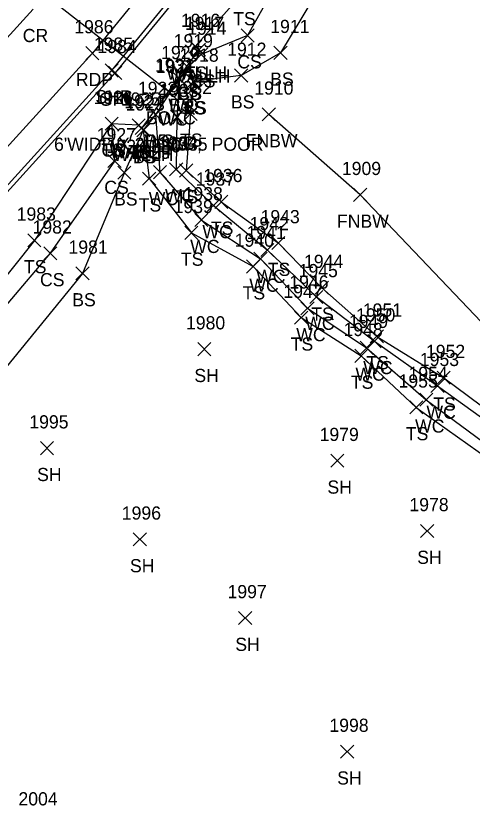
# Model space of a CAD drawing. Extents: x 1520648 to 1523413, y 732854 to 735518.
# Drawn here: x 1522252.1 to 1522321.3, y 733840.7 to 733961.6 of the extents above; entities that cross this region are included whole.
import ezdxf

# ---------------------------------------------------------------- set-up
doc = ezdxf.new("R2010")
doc.units = 0
for name, color, linetype in [('D_A', 7, 'Continuous'), ('D_C', 7, 'Continuous'), ('D_I', 7, 'Continuous'), ('D_TIC', 7, 'Continuous'), ('DDEFAULT', 7, 'Continuous'), ('DHW', 7, 'Continuous'), ('L_A', 7, 'Continuous'), ('L_I', 7, 'Continuous'), ('L_TIC', 7, 'Continuous'), ('LAWE', 7, 'Continuous'), ('LELB', 7, 'Continuous'), ('LFNC', 7, 'Continuous'), ('P_A', 7, 'Continuous'), ('P_I', 7, 'Continuous'), ('P_TIC', 7, 'Continuous'), ('PET', 7, 'Continuous'), ('PRC', 7, 'Continuous'), ('PSP', 7, 'Continuous'), ('R_A', 7, 'Continuous'), ('R_I', 7, 'Continuous'), ('R_TIC', 7, 'Continuous'), ('RGR', 7, 'Continuous')]:
    doc.layers.add(name, color=color, linetype=linetype)

msp = doc.modelspace()

# ---------------------------------------------------------------- linework, layer by layer
at = {"layer": 'D_TIC'}
for points in [[(1522278.32, 733955.93), (1522280.32, 733957.93)], [(1522280.32, 733955.93), (1522278.32, 733957.93)], [(1522278.87, 733955.47), (1522280.87, 733957.47)], [(1522280.87, 733955.47), (1522278.87, 733957.47)], [(1522274.31, 733949.11), (1522276.31, 733951.11)], [(1522276.31, 733949.11), (1522274.31, 733951.11)], [(1522269.74, 733943.98), (1522271.74, 733945.98)], [(1522271.74, 733943.98), (1522269.74, 733945.98)], [(1522270.22, 733943.58), (1522272.22, 733945.58)], [(1522272.22, 733943.58), (1522270.22, 733945.58)]]:
    msp.add_lwpolyline(points, dxfattribs=at)
at = {"layer": 'DDEFAULT'}
msp.add_lwpolyline([(1522243.41, 733975.06), (1522275.31, 733950.11)], dxfattribs=at)
at = {"layer": 'DHW'}
msp.add_lwpolyline([(1522279.32, 733956.93), (1522279.87, 733956.47), (1522271.22, 733944.58), (1522270.74, 733944.98)], dxfattribs=at)
at = {"layer": 'L_TIC'}
for points in [[(1522286.26, 733957.62), (1522288.26, 733959.62)], [(1522288.26, 733957.62), (1522286.26, 733959.62)], [(1522278.32, 733955.93), (1522280.32, 733957.93)], [(1522280.32, 733955.93), (1522278.32, 733957.93)], [(1522279.22, 733954.73), (1522281.22, 733956.73)], [(1522281.22, 733954.73), (1522279.22, 733956.73)], [(1522291.25, 733955), (1522293.25, 733957)], [(1522293.25, 733955), (1522291.25, 733957)], [(1522277.18, 733952.83), (1522279.18, 733954.83)], [(1522279.18, 733952.83), (1522277.18, 733954.83)], [(1522277.18, 733952.83), (1522279.18, 733954.83)], [(1522279.18, 733952.83), (1522277.18, 733954.83)], [(1522275.92, 733951.03), (1522277.92, 733953.03)], [(1522277.92, 733951.03), (1522275.92, 733953.03)], [(1522275.92, 733951.03), (1522277.92, 733953.03)], [(1522277.92, 733951.03), (1522275.92, 733953.03)], [(1522275.92, 733951.03), (1522277.92, 733953.03)], [(1522277.92, 733951.03), (1522275.92, 733953.03)], [(1522278.05, 733950.64), (1522280.05, 733952.64)], [(1522280.05, 733950.64), (1522278.05, 733952.64)], [(1522278.05, 733950.64), (1522280.05, 733952.64)], [(1522280.05, 733950.64), (1522278.05, 733952.64)], [(1522285.28, 733951.54), (1522287.28, 733953.54)], [(1522287.28, 733951.54), (1522285.28, 733953.54)], [(1522274.47, 733948.94), (1522276.47, 733950.94)], [(1522276.47, 733948.94), (1522274.47, 733950.94)], [(1522277.6, 733945.73), (1522279.6, 733947.73)], [(1522279.6, 733945.73), (1522277.6, 733947.73)], [(1522272.3, 733945.59), (1522274.3, 733947.59)], [(1522274.3, 733945.59), (1522272.3, 733947.59)], [(1522272.3, 733945.59), (1522274.3, 733947.59)], [(1522274.3, 733945.59), (1522272.3, 733947.59)], [(1522275.54, 733945.28), (1522277.54, 733947.28)], [(1522277.54, 733945.28), (1522275.54, 733947.28)], [(1522289.49, 733945.64), (1522291.49, 733947.64)], [(1522291.49, 733945.64), (1522289.49, 733947.64)], [(1522265.63, 733944.22), (1522267.63, 733946.22)], [(1522267.63, 733944.22), (1522265.63, 733946.22)], [(1522265.63, 733944.22), (1522267.63, 733946.22)], [(1522267.63, 733944.22), (1522265.63, 733946.22)], [(1522269.74, 733943.98), (1522271.74, 733945.98)], [(1522271.74, 733943.98), (1522269.74, 733945.98)], [(1522270.43, 733943.22), (1522272.43, 733945.22)], [(1522272.43, 733943.22), (1522270.43, 733945.22)], [(1522270.43, 733943.22), (1522272.43, 733945.22)], [(1522272.43, 733943.22), (1522270.43, 733945.22)], [(1522266.06, 733938.56), (1522268.06, 733940.56)], [(1522268.06, 733938.56), (1522266.06, 733940.56)], [(1522275.43, 733937.29), (1522277.43, 733939.29)], [(1522277.43, 733937.29), (1522275.43, 733939.29)], [(1522267.56, 733936.8), (1522269.56, 733938.8)], [(1522269.56, 733936.8), (1522267.56, 733938.8)], [(1522272.96, 733936.86), (1522274.96, 733938.86)], [(1522274.96, 733936.86), (1522272.96, 733938.86)], [(1522276.94, 733937.13), (1522278.94, 733939.13)], [(1522278.94, 733937.13), (1522276.94, 733939.13)], [(1522271.32, 733935.89), (1522273.32, 733937.89)], [(1522273.32, 733935.89), (1522271.32, 733937.89)], [(1522303.34, 733933.43), (1522305.34, 733935.43)], [(1522305.34, 733933.43), (1522303.34, 733935.43)], [(1522281.09, 733931.82), (1522283.09, 733933.82)], [(1522283.09, 733931.82), (1522281.09, 733933.82)], [(1522282.27, 733932.36), (1522284.27, 733934.36)], [(1522284.27, 733932.36), (1522282.27, 733934.36)], [(1522279.24, 733929.59), (1522281.24, 733931.59)], [(1522281.24, 733929.59), (1522279.24, 733931.59)], [(1522277.73, 733927.65), (1522279.73, 733929.65)], [(1522279.73, 733927.65), (1522277.73, 733929.65)], [(1522253.91, 733926.51), (1522255.91, 733928.51)], [(1522255.91, 733926.51), (1522253.91, 733928.51)], [(1522290.91, 733926.11), (1522292.91, 733928.11)], [(1522292.91, 733926.11), (1522290.91, 733928.11)], [(1522256.32, 733924.54), (1522258.32, 733926.54)], [(1522258.32, 733924.54), (1522256.32, 733926.54)], [(1522289.25, 733925.05), (1522291.25, 733927.05)], [(1522291.25, 733925.05), (1522289.25, 733927.05)], [(1522288.21, 733923.7), (1522290.21, 733925.7)], [(1522290.21, 733923.7), (1522288.21, 733925.7)], [(1522287.09, 733922.54), (1522289.09, 733924.54)], [(1522289.09, 733922.54), (1522287.09, 733924.54)], [(1522261.2, 733921.49), (1522263.2, 733923.49)], [(1522263.2, 733921.49), (1522261.2, 733923.49)], [(1522297.51, 733919.32), (1522299.51, 733921.32)], [(1522299.51, 733919.32), (1522297.51, 733921.32)], [(1522296.69, 733917.92), (1522298.69, 733919.92)], [(1522298.69, 733917.92), (1522296.69, 733919.92)], [(1522295.34, 733916.19), (1522297.34, 733918.19)], [(1522297.34, 733916.19), (1522295.34, 733918.19)], [(1522294.38, 733914.77), (1522296.38, 733916.77)], [(1522296.38, 733914.77), (1522294.38, 733916.77)], [(1522305.87, 733911.93), (1522307.87, 733913.93)], [(1522307.87, 733911.93), (1522305.87, 733913.93)], [(1522305.5, 733911.19), (1522307.5, 733913.19)], [(1522307.5, 733911.19), (1522305.5, 733913.19)], [(1522279.69, 733909.99), (1522281.69, 733911.99)], [(1522281.69, 733909.99), (1522279.69, 733911.99)], [(1522304.32, 733910.2), (1522306.32, 733912.2)], [(1522306.32, 733910.2), (1522304.32, 733912.2)], [(1522303.51, 733908.97), (1522305.51, 733910.97)], [(1522305.51, 733908.97), (1522303.51, 733910.97)], [(1522316.01, 733905.65), (1522318.01, 733907.65)], [(1522318.01, 733905.65), (1522316.01, 733907.65)], [(1522315.08, 733904.42), (1522317.08, 733906.42)], [(1522317.08, 733904.42), (1522315.08, 733906.42)], [(1522313.37, 733902.31), (1522315.37, 733904.31)], [(1522315.37, 733902.31), (1522313.37, 733904.31)], [(1522311.85, 733901.15), (1522313.85, 733903.15)], [(1522313.85, 733901.15), (1522311.85, 733903.15)], [(1522255.83, 733894.95), (1522257.83, 733896.95)], [(1522257.83, 733894.95), (1522255.83, 733896.95)], [(1522299.88, 733893.04), (1522301.88, 733895.04)], [(1522301.88, 733893.04), (1522299.88, 733895.04)], [(1522313.5, 733882.38), (1522315.5, 733884.38)], [(1522315.5, 733882.38), (1522313.5, 733884.38)], [(1522269.92, 733881.1), (1522271.92, 733883.1)], [(1522271.92, 733881.1), (1522269.92, 733883.1)], [(1522285.9, 733869.16), (1522287.9, 733871.16)], [(1522287.9, 733869.16), (1522285.9, 733871.16)], [(1522301.36, 733848.87), (1522303.36, 733850.87)], [(1522303.36, 733848.87), (1522301.36, 733850.87)]]:
    msp.add_lwpolyline(points, dxfattribs=at)
at = {"layer": 'LAWE'}
for points in [[(1522276.92, 733952.03), (1522275.47, 733949.94), (1522273.3, 733946.59), (1522273.96, 733937.86), (1522280.24, 733930.59), (1522289.21, 733924.7), (1522296.34, 733917.19), (1522305.32, 733911.2), (1522314.37, 733903.31), (1522328.27, 733893.01), (1522336.91, 733884.45), (1522339.19, 733873.29), (1522347.79, 733869.61), (1522363.19, 733860.75)], [(1522276.92, 733952.03), (1522276.54, 733946.28), (1522276.43, 733938.29), (1522282.09, 733932.82), (1522290.25, 733926.05), (1522297.69, 733918.92), (1522306.5, 733912.19), (1522316.08, 733905.42), (1522329.42, 733895.81), (1522338.19, 733885.32), (1522341.63, 733873.61), (1522347.73, 733871.15), (1522364.75, 733862.12)]]:
    msp.add_lwpolyline(points, dxfattribs=at)
at = {"layer": 'LELB'}
for points in [[(1522399.21, 734122.54), (1522383.71, 734100.99), (1522356.24, 734060.92), (1522336.35, 734027.13), (1522331.32, 734016.25), (1522299.59, 733987.37), (1522286.66, 733965.18), (1522279.32, 733956.93)], [(1522401.8, 734120.85), (1522386.75, 734098.22), (1522361.49, 734057.24), (1522340.39, 734023.47), (1522334.23, 734014.82), (1522302.26, 733985.56), (1522287.26, 733958.62), (1522280.22, 733955.73), (1522278.18, 733953.83)], [(1522392.7, 734094.89), (1522365.31, 734053.94), (1522345.12, 734021), (1522336.91, 734010.39), (1522307.1, 733980.69), (1522292.25, 733956), (1522286.28, 733952.54), (1522279.05, 733951.64), (1522278.18, 733953.83), (1522276.92, 733952.03)], [(1522279.05, 733951.64), (1522278.6, 733946.73), (1522277.94, 733938.13), (1522283.27, 733933.36), (1522291.91, 733927.11), (1522298.51, 733920.32), (1522306.87, 733912.93), (1522317.01, 733906.65), (1522330.24, 733896.82), (1522339.12, 733885.66), (1522342.73, 733873.76), (1522348.54, 733872.47), (1522366.14, 733862.6)], [(1522273.3, 733946.59), (1522271.43, 733944.22), (1522268.56, 733937.8), (1522262.2, 733922.49), (1522248.35, 733905.54), (1522225.71, 733875.09), (1522211.03, 733857.35), (1522192.48, 733835.82), (1522170.81, 733810.34), (1522151.93, 733786.41), (1522130.42, 733759.83), (1522111.64, 733741.03), (1522100.77, 733725.2)], [(1522266.63, 733945.22), (1522267.06, 733939.56), (1522257.32, 733925.54), (1522244.42, 733910.4), (1522223.41, 733883.18), (1522189.15, 733838.76), (1522168.77, 733813.86), (1522150.13, 733789.06), (1522128.4, 733762.92), (1522110.49, 733741.99), (1522098.34, 733726.66), (1522093.01, 733716.82)], [(1522270.74, 733944.98), (1522266.63, 733945.22), (1522254.91, 733927.51), (1522242.52, 733911.99), (1522219.52, 733884.24), (1522186.7, 733842.89), (1522166.07, 733817.07), (1522164.2, 733814.35), (1522137.24, 733813.36), (1522122.6, 733811.13)], [(1522271.43, 733944.22), (1522272.32, 733936.89), (1522278.73, 733928.65), (1522288.09, 733923.54), (1522295.38, 733915.77), (1522304.51, 733909.97), (1522312.85, 733902.15), (1522326.96, 733892.08), (1522335.67, 733883.7), (1522338.12, 733872.97), (1522347.65, 733868.91), (1522362.14, 733859.54)]]:
    msp.add_lwpolyline(points, dxfattribs=at)
at = {"layer": 'LFNC'}
msp.add_lwpolyline([(1522367.19, 733867.69), (1522349.23, 733888.51), (1522325.8, 733911.89), (1522304.34, 733934.43), (1522290.49, 733946.64)], dxfattribs=at)
at = {"layer": 'P_TIC'}
for points in [[(1522262.71, 733954.95), (1522264.71, 733956.95)], [(1522264.71, 733954.95), (1522262.71, 733956.95)], [(1522265.63, 733952.31), (1522267.63, 733954.31)], [(1522267.63, 733952.31), (1522265.63, 733954.31)]]:
    msp.add_lwpolyline(points, dxfattribs=at)
at = {"layer": 'PET'}
msp.add_lwpolyline([(1522293.19, 733992.18), (1522263.71, 733955.95), (1522232.46, 733921.59), (1522205.93, 733894.99), (1522171.68, 733864.45), (1522150.76, 733846.95), (1522111.89, 733818.73), (1522077.26, 733795.56), (1522046.35, 733777.35), (1522014.71, 733760.04), (1521992.39, 733748.52), (1521963.75, 733735.05), (1521947.25, 733727.94), (1521903.49, 733710.07), (1521845.39, 733690.65), (1521824.85, 733681.25), (1521803.81, 733674.87), (1521790.98, 733674.84), (1521764.05, 733667.92), (1521729.46, 733658.42), (1521691.16, 733648.14)], dxfattribs=at)
at = {"layer": 'PRC'}
msp.add_lwpolyline([(1522254.71, 733962.62), (1522224.2, 733929), (1522197.91, 733903), (1522164.25, 733873.02), (1522142.54, 733855.17), (1522104.41, 733827.43), (1522070.85, 733804.7), (1522039.57, 733786.25), (1522009.6, 733770.04), (1521986.99, 733758.56), (1521958.12, 733745.43), (1521942.23, 733738.37), (1521896.32, 733720.33), (1521857.71, 733706.32), (1521841.62, 733701.43), (1521812.17, 733692.84), (1521787.03, 733685.66), (1521768.25, 733680.62), (1521726.09, 733669.37), (1521688.17, 733658.56)], dxfattribs=at)
at = {"layer": 'PSP'}
msp.add_lwpolyline([(1522408.2, 734139.28), (1522381.04, 734102.47), (1522353.02, 734064.87), (1522324.01, 734025.28), (1522296.17, 733989.55), (1522266.63, 733953.31), (1522235.29, 733918.79), (1522209.78, 733890.98), (1522201.9, 733884.12), (1522173.49, 733859.11), (1522154.03, 733843.41), (1522113.55, 733816.07), (1522079.34, 733793.19), (1522048.3, 733774.46), (1522016.59, 733757.42), (1521993.94, 733745.83), (1521965.16, 733732.44), (1521948.66, 733724.97), (1521904.28, 733707.61), (1521888.63, 733701.99), (1521847.29, 733686.72), (1521809.29, 733673.67)], dxfattribs=at)
at = {"layer": 'R_TIC'}
for points in [[(1522266.17, 733951.95), (1522268.17, 733953.95)], [(1522268.17, 733951.95), (1522266.17, 733953.95)]]:
    msp.add_lwpolyline(points, dxfattribs=at)
at = {"layer": 'RGR'}
msp.add_lwpolyline([(1522327.77, 734020.69), (1522316.41, 734013), (1522308.3, 734003.69), (1522296.64, 733988.96), (1522267.17, 733952.95), (1522235.76, 733918.25), (1522219.05, 733899.75), (1522212.83, 733888.73)], dxfattribs=at)

# ---------------------------------------------------------------- texts
at = {"layer": 'D_A'}
for s, p in [('WALLH', (1522274.91, 733951.93)), ('WALLH', (1522275.46, 733951.47)), ('BOXC', (1522271.81, 733945.11)), ('WALLH', (1522266.33, 733939.98)), ('WALLH', (1522266.81, 733939.58))]:
    msp.add_text(s, height=2, dxfattribs=at).set_placement(p)
at = {"layer": 'D_C'}
msp.add_text("6'WIDE X 2' HIGH,  POOR", height=2, dxfattribs=at).set_placement((1522257.89, 733941.11))
at = {"layer": 'D_I'}
for s, p in [('1916', (1522277.14, 733959.93)), ('1917', (1522277.74, 733959.47)), ('1931', (1522273.19, 733953.11)), ('1925', (1522268.05, 733947.98)), ('1924', (1522268.53, 733947.58))]:
    msp.add_text(s, height=2, dxfattribs=at).set_placement(p)
at = {"layer": 'L_A'}
for s, p in [('TS', (1522285.07, 733960.18)), ('CS', (1522285.7, 733953.62)), ('TS', (1522277.73, 733951.93)), ('CS', (1522278.66, 733950.73)), ('BS', (1522290.69, 733951)), ('CS', (1522276.63, 733948.83)), ('BS', (1522276.63, 733948.83)), ('WC', (1522275.23, 733947.03)), ('WC', (1522275.23, 733947.03)), ('BS', (1522275.36, 733947.03)), ('BS', (1522284.73, 733947.54)), ('TS', (1522277.45, 733946.64)), ('BS', (1522277.49, 733946.64)), ('WC', (1522273.77, 733944.94)), ('WC', (1522271.61, 733941.59)), ('BS', (1522271.74, 733941.59)), ('WC', (1522274.85, 733941.28)), ('TS', (1522277.01, 733941.73)), ('FNBW', (1522286.96, 733941.64)), ('TS', (1522265.04, 733940.22)), ('CS', (1522265.07, 733940.22)), ('TS', (1522269.15, 733939.98)), ('TS', (1522269.84, 733939.22)), ('BS', (1522269.87, 733939.22)), ('CS', (1522265.51, 733934.56)), ('BS', (1522267, 733932.8)), ('WC', (1522272.26, 733932.86)), ('WC', (1522274.73, 733933.29)), ('TS', (1522276.35, 733933.13)), ('TS', (1522270.73, 733931.89)), ('FNBW', (1522300.81, 733929.43)), ('WC', (1522280.4, 733927.82)), ('TS', (1522281.68, 733928.36)), ('WC', (1522278.55, 733925.59)), ('TS', (1522277.14, 733923.65)), ('TS', (1522253.32, 733922.51)), ('TS', (1522290.32, 733922.11)), ('CS', (1522255.76, 733920.54)), ('WC', (1522288.56, 733921.05)), ('WC', (1522287.52, 733919.7)), ('TS', (1522286.5, 733918.54)), ('BS', (1522260.65, 733917.49)), ('TS', (1522296.92, 733915.32)), ('WC', (1522296, 733913.92)), ('WC', (1522294.64, 733912.19)), ('TS', (1522293.79, 733910.77)), ('WC', (1522304.8, 733907.19)), ('TS', (1522305.28, 733907.93)), ('SH', (1522279.18, 733905.99)), ('WC', (1522303.62, 733906.2)), ('TS', (1522302.92, 733904.97)), ('TS', (1522315.42, 733901.65)), ('WC', (1522314.39, 733900.42)), ('WC', (1522312.67, 733898.31)), ('TS', (1522311.26, 733897.15)), ('SH', (1522255.32, 733890.95)), ('SH', (1522299.37, 733889.04)), ('SH', (1522312.99, 733878.38)), ('SH', (1522269.41, 733877.1)), ('SH', (1522285.39, 733865.16)), ('SH', (1522300.85, 733844.87))]:
    msp.add_text(s, height=2, dxfattribs=at).set_placement(p)
at = {"layer": 'L_I'}
for s, p in [('1916', (1522277.14, 733959.93)), ('1911', (1522290.69, 733959)), ('1914', (1522278.1, 733958.73)), ('1919', (1522276.05, 733956.83)), ('1919', (1522276.05, 733956.83)), ('1912', (1522284.16, 733955.54)), ('1920', (1522274.14, 733955.03)), ('1920', (1522274.14, 733955.03)), ('1920', (1522274.14, 733955.03)), ('1918', (1522276.92, 733954.64)), ('1918', (1522276.92, 733954.64)), ('1921', (1522273.34, 733952.94)), ('1922', (1522270.61, 733949.59)), ('1922', (1522270.61, 733949.59)), ('1932', (1522275.91, 733949.73)), ('1910', (1522288.27, 733949.64)), ('1926', (1522263.88, 733948.22)), ('1926', (1522263.88, 733948.22)), ('1933', (1522273.85, 733949.28)), ('1925', (1522268.05, 733947.98)), ('1923', (1522268.74, 733947.22)), ('1923', (1522268.74, 733947.22)), ('1927', (1522264.37, 733942.56)), ('1930', (1522271.18, 733940.86)), ('1934', (1522273.73, 733941.29)), ('1935', (1522275.24, 733941.13)), ('1928', (1522265.87, 733940.8)), ('1929', (1522269.62, 733939.89)), ('1909', (1522301.56, 733937.43)), ('1936', (1522280.53, 733936.36)), ('1937', (1522279.4, 733935.82)), ('1938', (1522277.55, 733933.59)), ('1939', (1522276.03, 733931.65)), ('1983', (1522252.22, 733930.51)), ('1943', (1522289.22, 733930.11)), ('1942', (1522287.56, 733929.05)), ('1982', (1522254.63, 733928.54)), ('1941', (1522287.09, 733927.7)), ('1940', (1522285.31, 733926.54)), ('1981', (1522260.08, 733925.49)), ('1944', (1522295.82, 733923.32)), ('1945', (1522295, 733921.92)), ('1946', (1522293.59, 733920.19)), ('1947', (1522292.69, 733918.77)), ('1951', (1522304.74, 733915.93)), ('1950', (1522303.72, 733915.19)), ('1980', (1522277.91, 733913.99)), ('1949', (1522302.62, 733914.2)), ('1948', (1522301.81, 733912.97)), ('1952', (1522314.32, 733909.65)), ('1953', (1522313.39, 733908.42)), ('1954', (1522311.67, 733906.31)), ('1955', (1522310.16, 733905.15)), ('1995', (1522254.14, 733898.95)), ('1979', (1522298.18, 733897.04)), ('1978', (1522311.81, 733886.38)), ('1996', (1522268.17, 733885.1)), ('1997', (1522284.21, 733873.16)), ('1998', (1522299.67, 733852.87)), ('2004', (1522252.49, 733841.7))]:
    msp.add_text(s, height=2, dxfattribs=at).set_placement(p)
at = {"layer": 'P_A'}
for s, p in [('CR', (1522253.14, 733957.62)), ('RDP', (1522261.2, 733950.95)), ('SHP', (1522264.16, 733948.31))]:
    msp.add_text(s, height=2, dxfattribs=at).set_placement(p)
at = {"layer": 'P_I'}
for s, p in [('1986', (1522260.96, 733958.95)), ('1985', (1522263.93, 733956.31))]:
    msp.add_text(s, height=2, dxfattribs=at).set_placement(p)
at = {"layer": 'R_A'}
msp.add_text('GRL', height=2, dxfattribs=at).set_placement((1522264.71, 733947.95))
at = {"layer": 'R_I'}
msp.add_text('1984', height=2, dxfattribs=at).set_placement((1522264.47, 733955.95))

doc.saveas('drawing.dxf')
